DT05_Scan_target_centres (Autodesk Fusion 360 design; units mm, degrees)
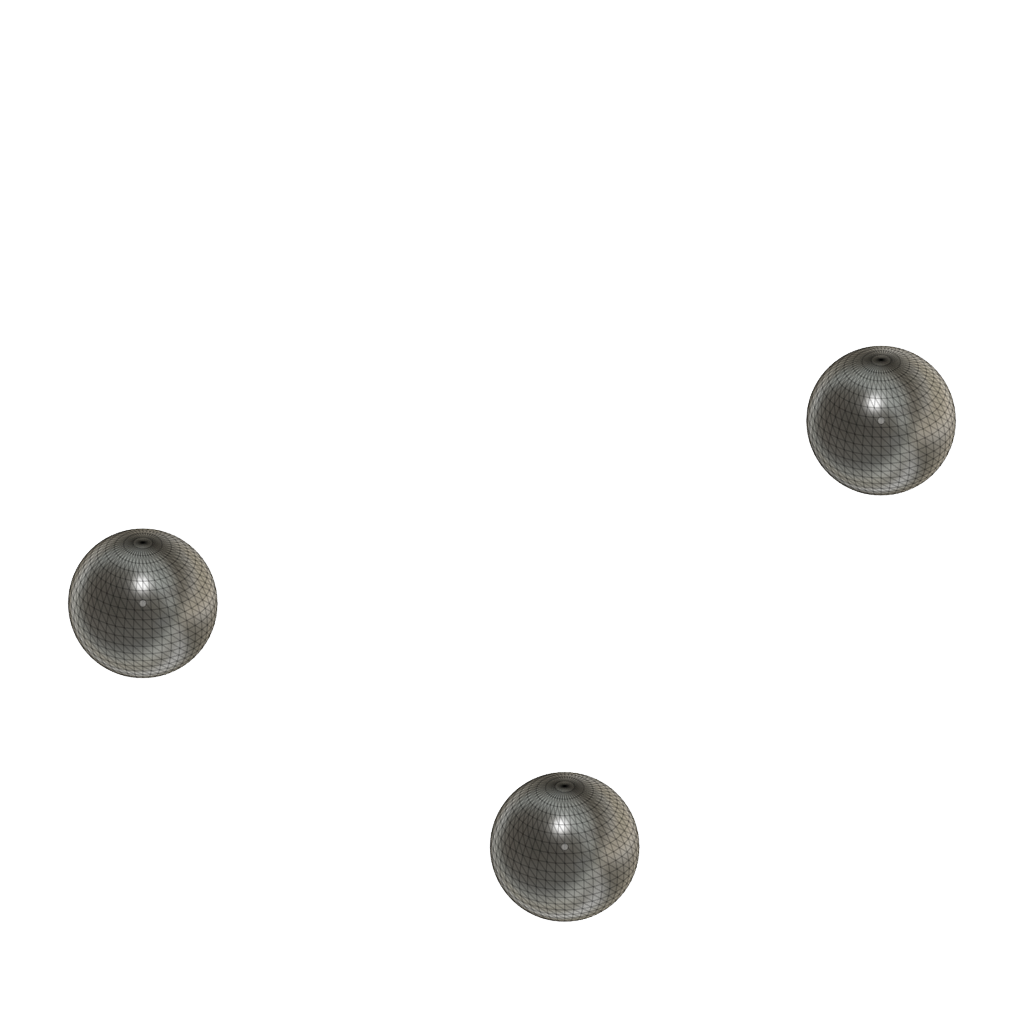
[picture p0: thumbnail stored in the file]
part number: 2026-10-26-12-19-12-554
base_mesh_feature "Base Mesh Feature"
sketch "Scan targets" plane through (0, 0, 0) normal (0, 0, 1) x axis (1, 0, 0)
